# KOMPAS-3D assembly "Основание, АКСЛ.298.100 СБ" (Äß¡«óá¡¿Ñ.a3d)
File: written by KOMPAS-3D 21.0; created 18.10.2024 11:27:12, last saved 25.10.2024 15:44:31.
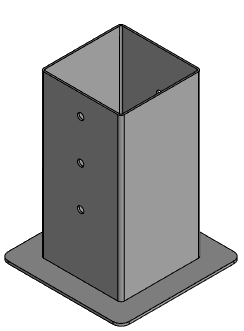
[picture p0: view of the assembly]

Document properties: Полное имя файла: C:\Users\Алексей Бочаров\YandexDisk\Соединения бруса\Соединения бруса\ОСНОВАНИЕ\Основание.a3d; Автор: Алексей Бочаров

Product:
- Part/product: Основание  | designation АКСЛ.298.100 СБ
    Масса: 1.739154
    Форматы листов документа: A2
    source file: Основание спецификация.spw
  - Component [detail]: Пластина основания  | designation АКСЛ.298.101  | pos. 1  | Масса: 0.528257; Форматы листов документа: A4; source file: Пластина основания.cdw, Пластина основания.m3d
  - Component [detail]: Профиль L = 200 мм  | designation АКСЛ.298.401  | pos. 2  | Масса: 1.210897; source file: ..\КВАТРО\АКСЛ.298.401 - Профиль L = 200 мм.cdw, ..\КВАТРО\Профиль L = 200 мм.m3d

Referenced files in C:\Users\Алексей Бочаров\YandexDisk\Соединения бруса\Соединения бруса\ОСНОВАНИЕ\: Пластина основания.m3d
Referenced files in C:\Users\Алексей Бочаров\YandexDisk\Соединения бруса\Соединения бруса\КВАТРО\: Профиль L = 200 мм.m3d
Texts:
  АКСЛ.298.100 СБ
  АКСЛ.298.101 Пластина основания
  АКСЛ.298.401 Профиль L = 200 мм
